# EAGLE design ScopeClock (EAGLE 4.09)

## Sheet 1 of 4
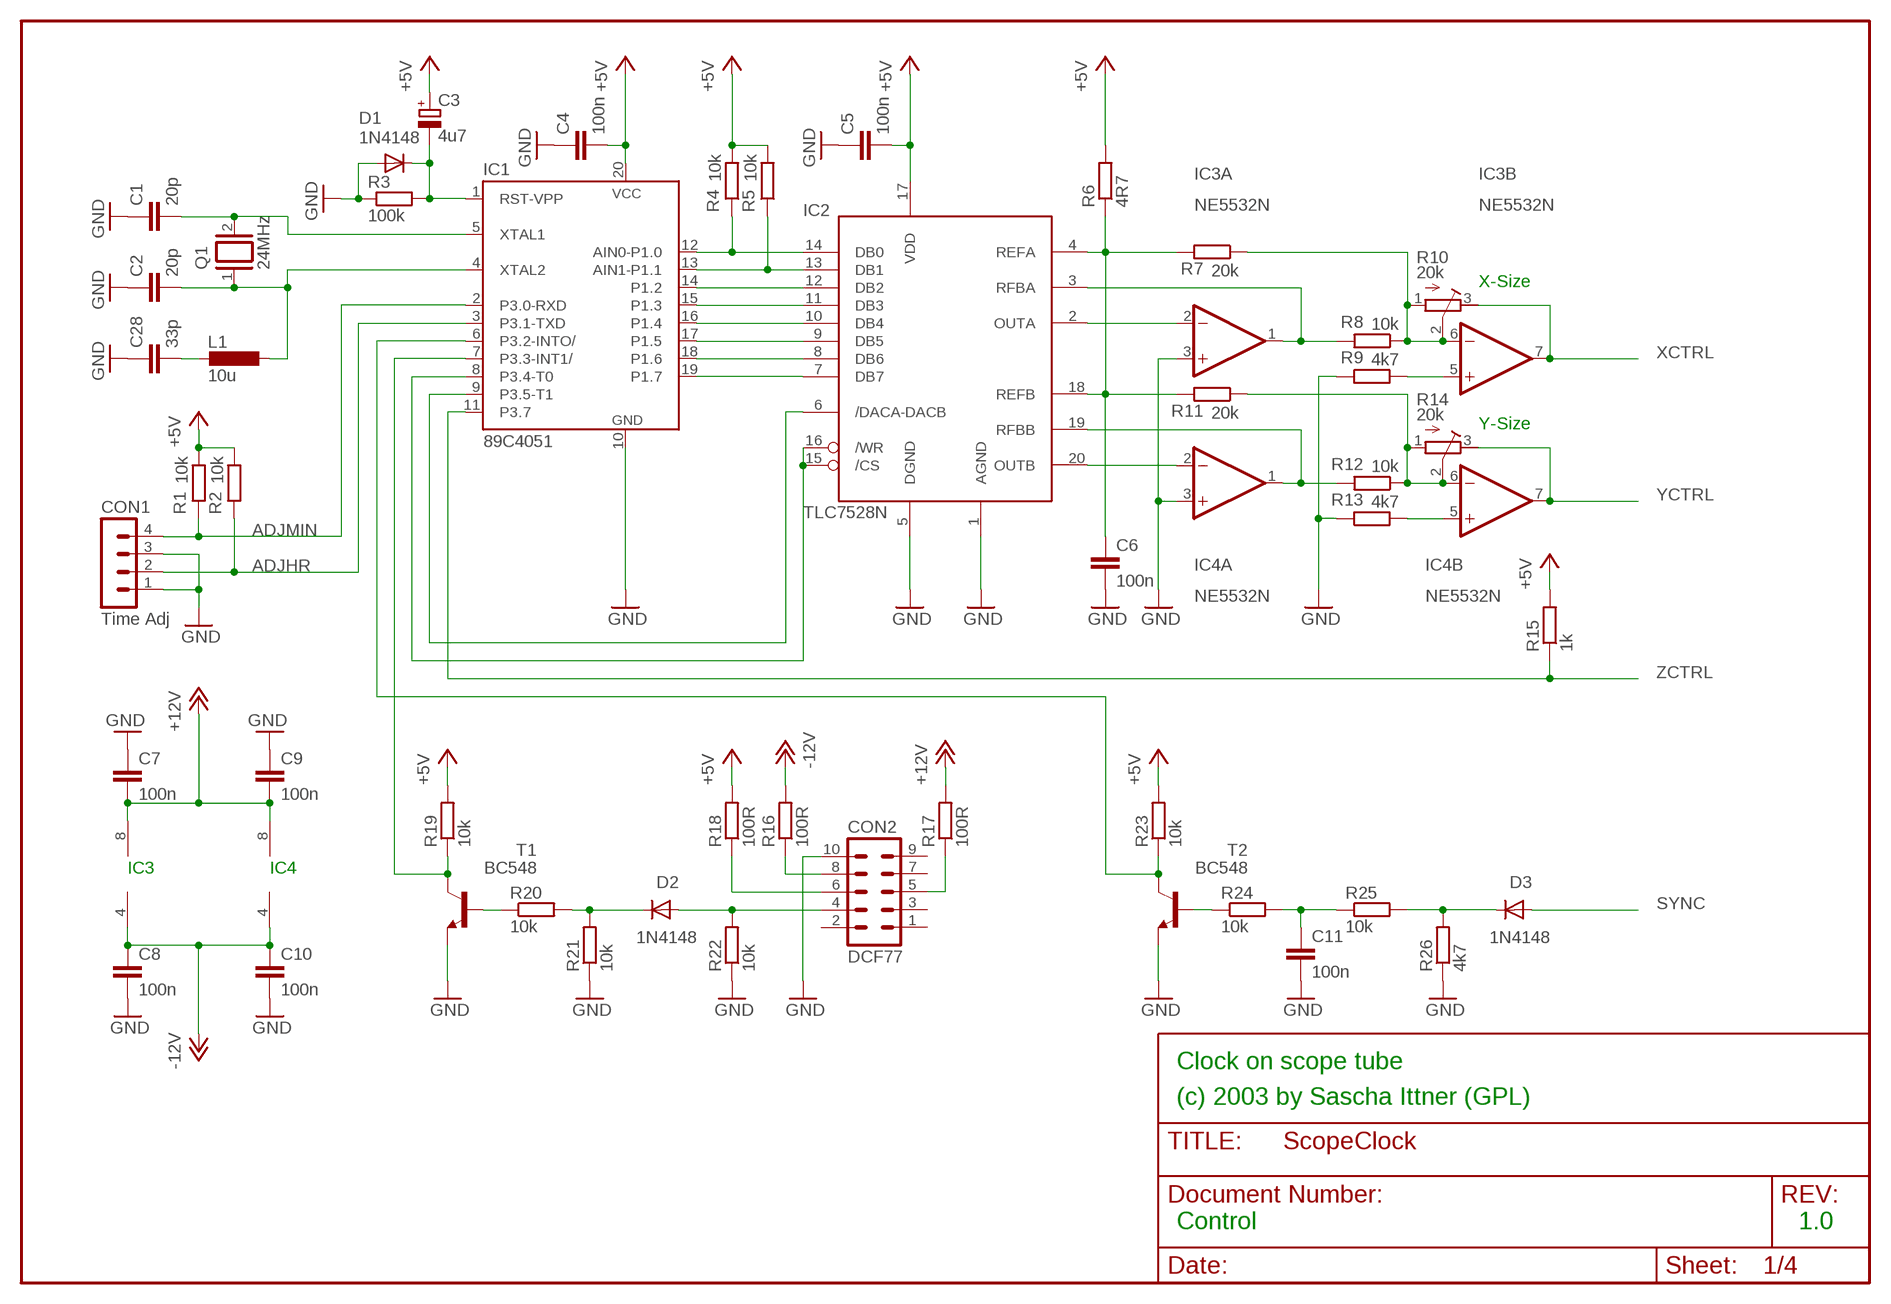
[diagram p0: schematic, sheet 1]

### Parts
C1  20p  C-EU025-024X044  [C025-024X044]
C2  20p  C-EU025-024X044  [C025-024X044]
C3  4u7  CPOL-EUE5-5  [E5-5]
C4  100n  C-EU050-024X044  [C050-024X044]
C5  100n  C-EU050-024X044  [C050-024X044]
C6  100n  C-EU050-024X044  [C050-024X044]
C7  100n  C-EU050-024X044  [C050-024X044]
C8  100n  C-EU050-024X044  [C050-024X044]
C9  100n  C-EU050-024X044  [C050-024X044]
C10  100n  C-EU050-024X044  [C050-024X044]
C11  100n  C-EU050-024X044  [C050-024X044]
C28  33p  C-EU025-024X044  [C025-024X044]
CON1  Time Adj  MA04-1  [MA04-1]
CON2  DCF77  ML10  [ML10]
D1  1N4148  [DO35-10]
D2  1N4148  [DO35-10]
D3  1N4148  [DO35-10]
IC1  89C4051  [DIL20]
IC2  TLC7528N  [DIL20]
IC3  NE5532N  [DIL08]
IC4  NE5532N  [DIL08]
L1  10u  L-EU0207/12  [0207/12]
Q1  24MHz  XTAL/S  [QS]
R1  10k  R-EU_0207/7  [0207/7]
R2  10k  R-EU_0207/7  [0207/7]
R3  100k  R-EU_0207/7  [0207/7]
R4  10k  R-EU_0207/7  [0207/7]
R5  10k  R-EU_0207/7  [0207/7]
R6  4R7  R-EU_0207/7  [0207/7]
R7  20k  R-EU_0207/7  [0207/7]
R8  10k  R-EU_0207/7  [0207/7]
R9  4k7  R-EU_0207/7  [0207/7]
R10  20k  R-TRIMM64W  [RTRIM64W]
R11  20k  R-EU_0207/7  [0207/7]
R12  10k  R-EU_0207/7  [0207/7]
R13  4k7  R-EU_0207/7  [0207/7]
R14  20k  R-TRIMM64W  [RTRIM64W]
R15  1k  R-EU_0207/7  [0207/7]
R16  100R  R-EU_0207/7  [0207/7]
R17  100R  R-EU_0207/7  [0207/7]
R18  100R  R-EU_0207/7  [0207/7]
R19  10k  R-EU_0207/7  [0207/7]
R20  10k  R-EU_0207/7  [0207/7]
R21  10k  R-EU_0207/7  [0207/7]
R22  10k  R-EU_0207/7  [0207/7]
R23  10k  R-EU_0207/7  [0207/7]
R24  10k  R-EU_0207/7  [0207/7]
R25  10k  R-EU_0207/7  [0207/7]
R26  4k7  R-EU_0207/7  [0207/7]
T1  BC548  [TO92-EBC]
T2  BC548  [TO92-EBC]

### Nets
+5V: C3.+ C4.2 C5.2 IC1.20(VCC) IC2.17(VDD) R1.2 R2.2 R4.2 R5.2 R6.2 R15.2 R18.2 R19.2 R23.2 ; also sheet 3
+12V: C7.2 C9.2 IC3.8(P:V+) IC4.8(P:V+) R17.2 ; also sheet 2,3
-12V: C8.1 C10.1 IC3.4(P:V-) IC4.4(P:V-) R16.2 ; also sheet 3
ADJHR: CON1.2 IC1.3(P3.1-TXD) R2.1
ADJMIN: CON1.4 IC1.2(P3.0-RXD) R1.1
GND: C1.1 C2.1 C4.1 C5.1 C6.2 C7.1 C8.2 C9.1 C10.2 C11.2 C28.1 CON1.1 CON1.3 CON2.10 D1.A IC1.10(GND) IC2.1(AGND) IC2.5(DGND) IC3.3(A:+IN) IC4.3(A:+IN) R3.1 R9.1 R13.1 R21.1 R22.1 R26.1 T1.E T2.E ; also sheet 2,3,4
N$1: IC1.12(AIN0-P1.0) IC2.14(DB0) R4.1
N$2: IC1.13(AIN1-P1.1) IC2.13(DB1) R5.1
N$3: IC1.14(P1.2) IC2.12(DB2)
N$4: IC1.15(P1.3) IC2.11(DB3)
N$5: IC1.16(P1.4) IC2.10(DB4)
N$6: IC1.17(P1.5) IC2.9(DB5)
N$7: IC1.18(P1.6) IC2.8(DB6)
N$8: IC1.19(P1.7) IC2.7(DB7)
N$9: IC1.9(P3.5-T1) IC2.6(/DACA-DACB)
N$10: IC1.8(P3.4-T0) IC2.15(/CS) IC2.16(/WR)
N$11: IC2.2(OUTA) IC3.2(A:-IN)
N$12: IC2.20(OUTB) IC4.2(A:-IN)
N$13: IC2.3(RFBA) IC3.1(A:OUT) R8.2
N$14: IC2.19(RFBB) IC4.1(A:OUT) R12.2
N$15: C6.1 IC2.4(REFA) IC2.18(REFB) R6.1 R7.2 R11.2
N$16: CON2.4 D2.A R22.2
N$17: IC3.5(B:+IN) R9.2
N$18: IC4.5(B:+IN) R13.2
N$19: IC3.6(B:-IN) R7.1 R8.1 R10.1(E) R10.2(S)
N$20: IC4.6(B:-IN) R11.1 R12.1 R14.1(E) R14.2(S)
N$21: C3.- D1.C IC1.1(RST-VPP) R3.2
N$25: C1.2 IC1.5(XTAL1) Q1.2
N$26: C2.2 IC1.4(XTAL2) L1.1 Q1.1
N$28: CON2.8 R16.1
N$29: CON2.6 R18.1
N$30: CON2.5 R17.1
N$31: IC1.6(P3.2-INTO/) R23.1 T2.C
N$32: C11.1 R24.2 R25.1
N$35: R20.1 T1.B
N$36: D2.C R20.2 R21.2
N$38: D3.C R25.2 R26.2
N$40: IC1.7(P3.3-INT1/) R19.1 T1.C
N$41: R24.1 T2.B
N$77: C28.2 L1.2
SYNC: D3.A ; also sheet 3
XCTRL: IC3.7(B:OUT) R10.3(A) ; also sheet 2
YCTRL: IC4.7(B:OUT) R14.3(A) ; also sheet 2
ZCTRL: IC1.11(P3.7) R15.1 ; also sheet 2
Unconnected: CON2.1 CON2.2 CON2.3 CON2.7 CON2.9

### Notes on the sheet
- X-Size
- Y-Size
- IC3 | IC4
- Clock on scope tube
- (c) 2003 by Sascha Ittner (GPL)
- Control | 1.0

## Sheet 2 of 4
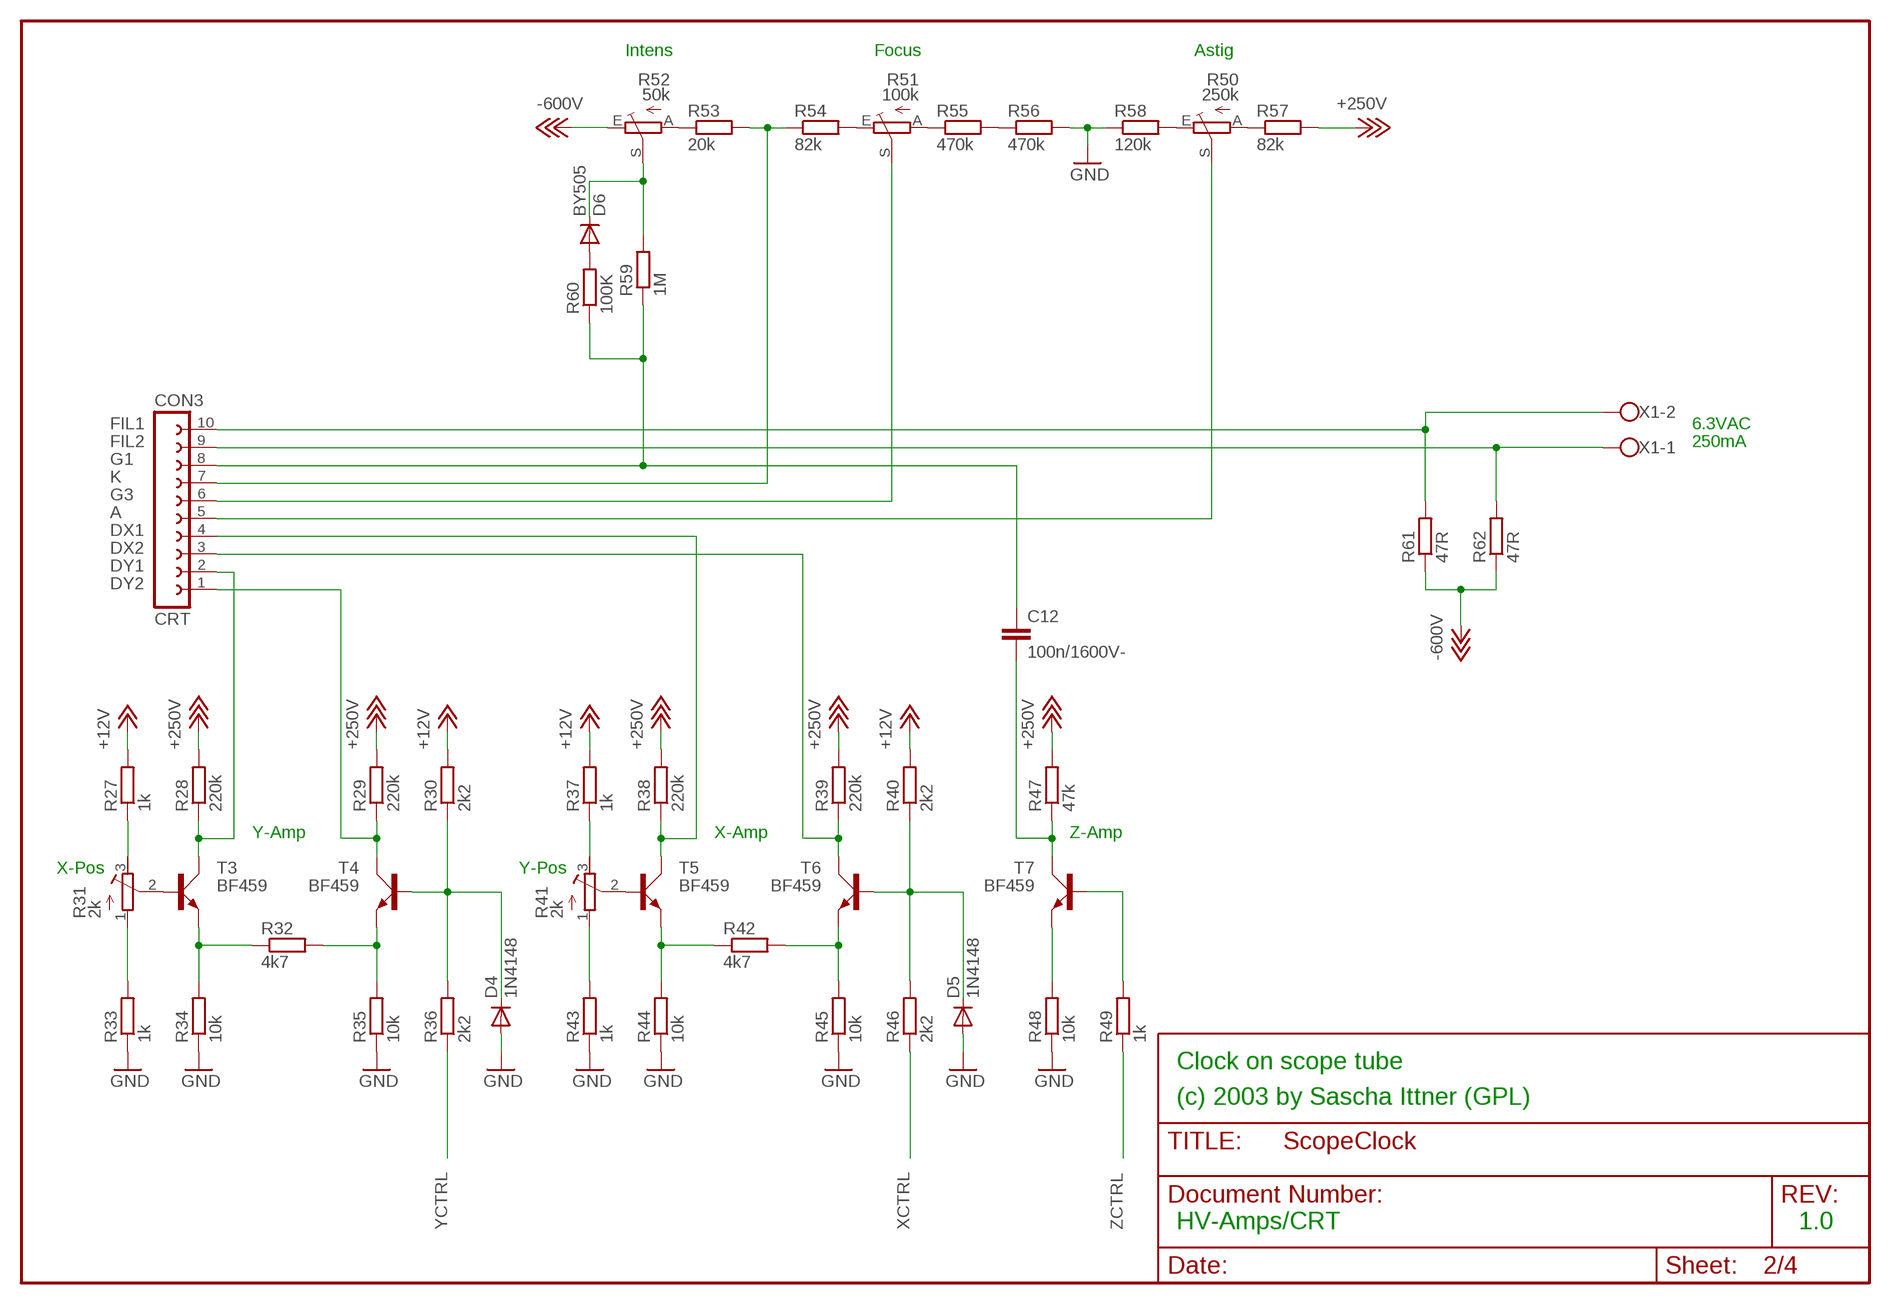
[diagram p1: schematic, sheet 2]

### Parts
C12  100n/1600V-  C-EU225-113X268  [C225-113X268]
CON3  CRT  FE10-1  [FE10]
D4  1N4148  [DO35-10]
D5  1N4148  [DO35-10]
D6  BY505  [SOD61A]
R27  1k  R-EU_0207/7  [0207/7]
R28  220k  R-EU_0207/7  [0207/7]
R29  220k  R-EU_0207/7  [0207/7]
R30  2k2  R-EU_0207/7  [0207/7]
R31  2k  R-TRIMM64W  [RTRIM64W]
R32  4k7  R-EU_0207/7  [0207/7]
R33  1k  R-EU_0207/7  [0207/7]
R34  10k  R-EU_0207/7  [0207/7]
R35  10k  R-EU_0207/7  [0207/7]
R36  2k2  R-EU_0207/7  [0207/7]
R37  1k  R-EU_0207/7  [0207/7]
R38  220k  R-EU_0207/7  [0207/7]
R39  220k  R-EU_0207/7  [0207/7]
R40  2k2  R-EU_0207/7  [0207/7]
R41  2k  R-TRIMM64W  [RTRIM64W]
R42  4k7  R-EU_0207/7  [0207/7]
R43  1k  R-EU_0207/7  [0207/7]
R44  10k  R-EU_0207/7  [0207/7]
R45  10k  R-EU_0207/7  [0207/7]
R46  2k2  R-EU_0207/7  [0207/7]
R47  47k  R-EU_0207/7  [0207/7]
R48  10k  R-EU_0207/7  [0207/7]
R49  1k  R-EU_0207/7  [0207/7]
R50  250k  TRIM_EU-S63P  [S63P]
R51  100k  TRIM_EU-S63P  [S63P]
R52  50k  TRIM_EU-S63P  [S63P]
R53  20k  R-EU_0207/7  [0207/7]
R54  82k  R-EU_0207/7  [0207/7]
R55  470k  R-EU_0207/7  [0207/7]
R56  470k  R-EU_0207/7  [0207/7]
R57  82k  R-EU_0207/7  [0207/7]
R58  120k  R-EU_0207/7  [0207/7]
R59  1M  R-EU_0207/7  [0207/7]
R60  100K  R-EU_0207/7  [0207/7]
R61  47R  R-EU_0207/7  [0207/7]
R62  47R  R-EU_0207/7  [0207/7]
T3  BF459  BD139  [TO126AV]
T4  BF459  BD139  [TO126AV]
T5  BF459  BD139  [TO126AV]
T6  BF459  BD139  [TO126AV]
T7  BF459  BD139  [TO126AV]
X1  W237-102  [W237-102]

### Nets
+12V: R27.2 R30.2 R37.2 R40.2 ; also sheet 1,3
+18V [HV]: R28.2 R29.2 R38.2 R39.2 R47.2 R57.2 ; supply symbol labelled +250V ; also sheet 4
-18V [VHV]: R52.E R61.1 R62.1 ; supply symbol labelled -600V ; also sheet 4
A [HV]: CON3.5 R50.S
DX1 [HV]: CON3.3 R39.1 T6.C
DX2 [HV]: CON3.4 R38.1 T5.C
DY1 [HV]: CON3.1 R29.1 T4.C
DY2 [HV]: CON3.2 R28.1 T3.C
FIL1 [VHV]: CON3.10 R61.2 X1.2
FIL2 [VHV]: CON3.9 R62.2 X1.1
G1 [VHV]: C12.1 CON3.8 R59.1 R60.1
G3: CON3.6 R51.S
GND: D4.A D5.A R33.1 R34.1 R35.1 R43.1 R44.1 R45.1 R48.1 R56.2 R58.1 ; also sheet 1,3,4
K [VHV]: CON3.7 R53.2 R54.1
N$22: R31.2(S) T3.B
N$23: R31.1(E) R33.2
N$24: R32.1 R34.2 T3.E
N$27: R41.2(S) T5.B
N$33: R32.2 R35.2 T4.E
N$34: R41.1(E) R43.2
N$37: D4.C R30.1 R36.2 T4.B
N$43: R27.1 R31.3(A)
N$44: R42.1 R44.2 T5.E
N$45: R37.1 R41.3(A)
N$46: R42.2 R45.2 T6.E
N$48: D5.C R40.1 R46.2 T6.B
N$49: R48.2 T7.E
N$50 [HV]: C12.2 R47.1 T7.C
N$52 [VHV]: R52.A R53.1
N$53 [VHV]: R51.E R54.2
N$54: R49.2 T7.B
N$55 [VHV]: R51.A R55.1
N$56 [HV]: R50.A R57.1
N$57 [HV]: R55.2 R56.1
N$58 [HV]: R50.E R58.2
N$69 [VHV]: D6.A R60.2
N$70 [VHV]: D6.C R52.S R59.2
XCTRL: R46.1 ; also sheet 1
YCTRL: R36.1 ; also sheet 1
ZCTRL: R49.1 ; also sheet 1

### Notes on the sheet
- Intens | Focus | Astig
- 6.3VAC
- 250mA
- Y-Amp | X-Amp | Z-Amp
- X-Pos | Y-Pos
- Clock on scope tube
- (c) 2003 by Sascha Ittner (GPL)
- HV-Amps/CRT | 1.0

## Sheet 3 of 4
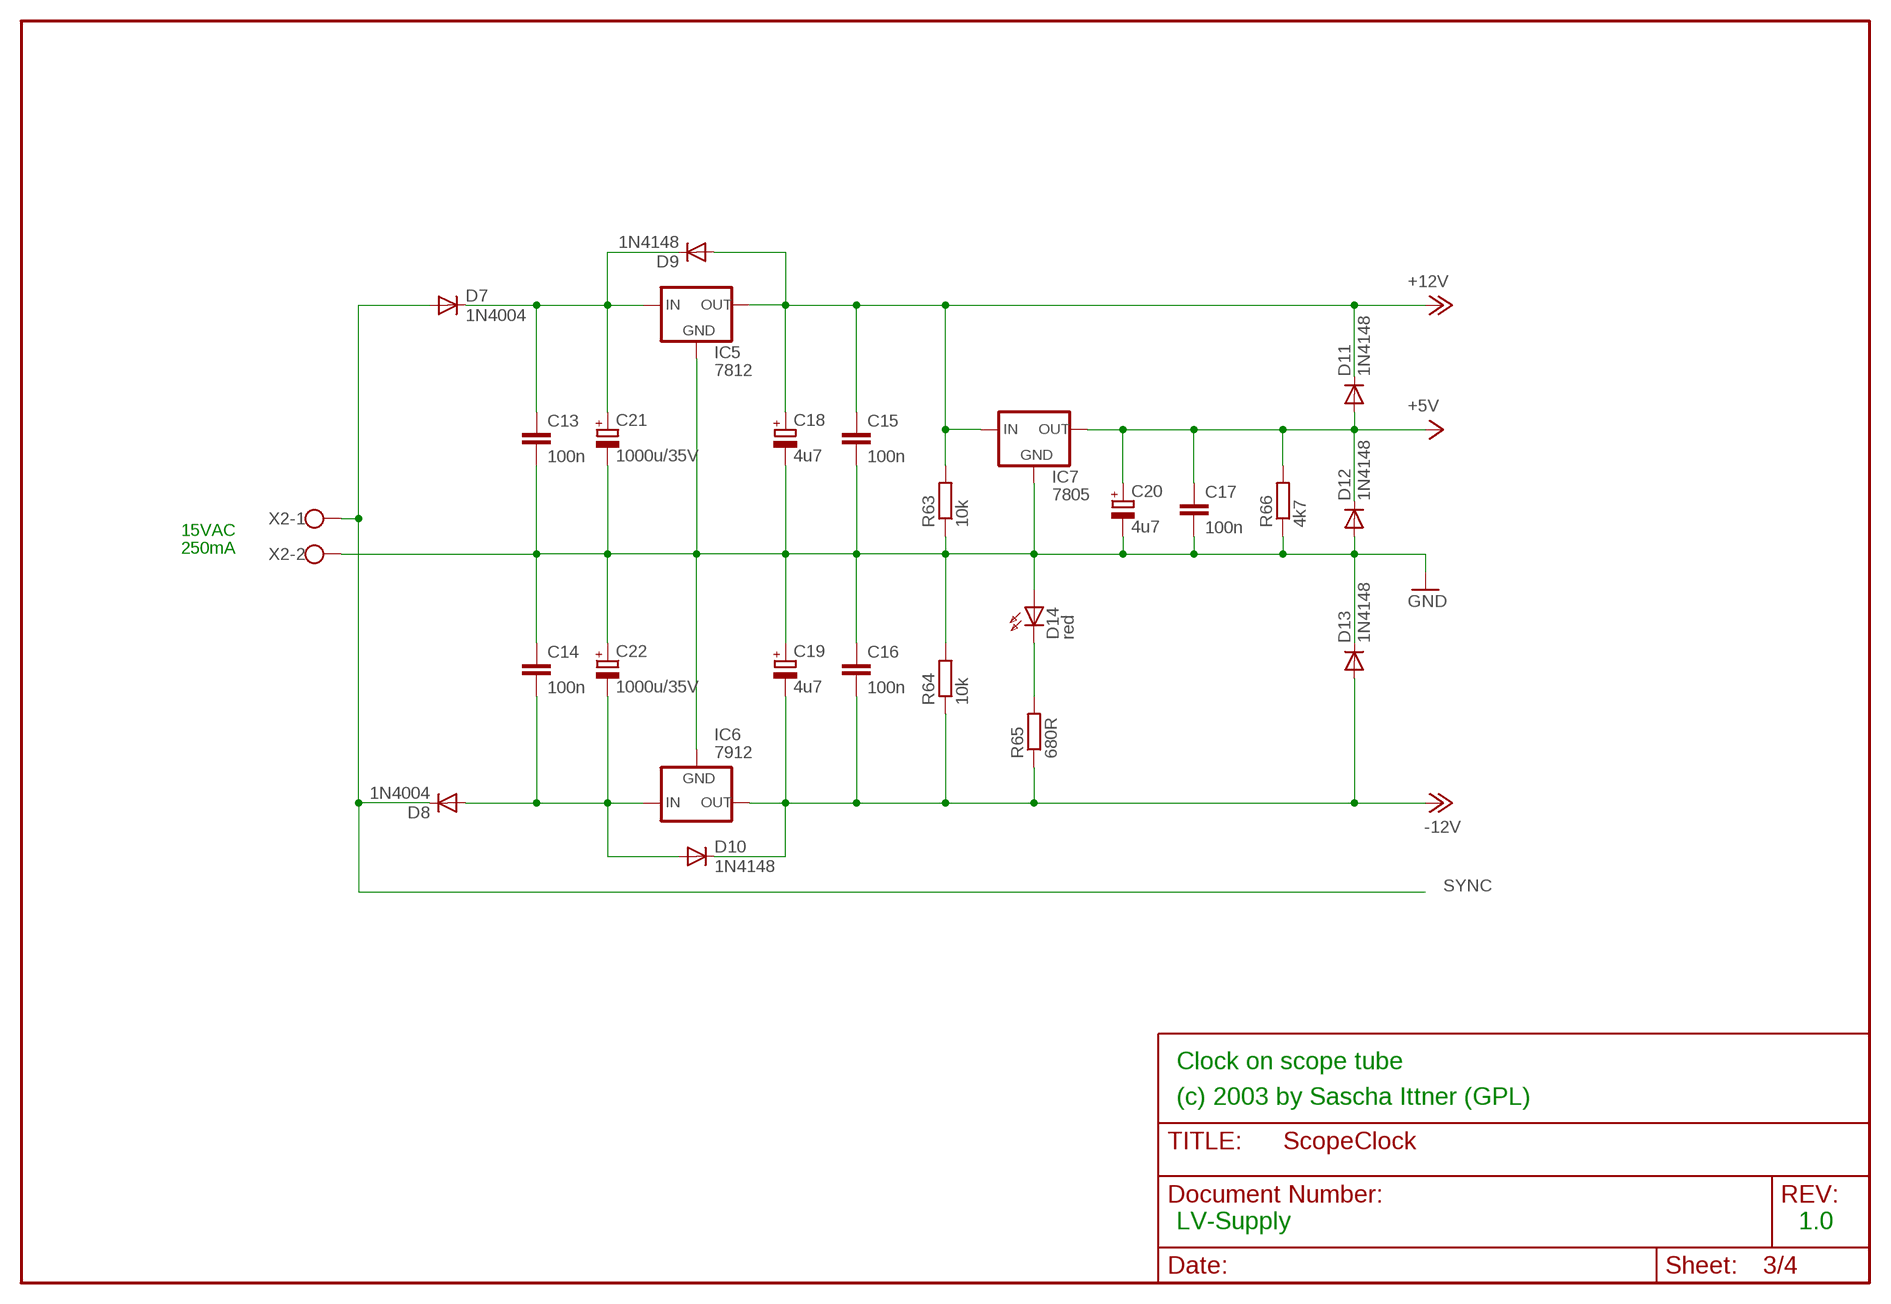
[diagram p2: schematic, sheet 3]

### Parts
C13  100n  C-EU050-024X044  [C050-024X044]
C14  100n  C-EU050-024X044  [C050-024X044]
C15  100n  C-EU050-024X044  [C050-024X044]
C16  100n  C-EU050-024X044  [C050-024X044]
C17  100n  C-EU050-024X044  [C050-024X044]
C18  4u7  CPOL-EUE2.5-5  [E2,5-5]
C19  4u7  CPOL-EUE2.5-5  [E2,5-5]
C20  4u7  CPOL-EUE2.5-5  [E2,5-5]
C21  1000u/35V  CPOL-EUE5-13  [E5-13]
C22  1000u/35V  CPOL-EUE5-13  [E5-13]
D7  1N4004  [DO41-10]
D8  1N4004  [DO41-10]
D9  1N4148  [DO35-10]
D10  1N4148  [DO35-10]
D11  1N4148  [DO35-10]
D12  1N4148  [DO35-10]
D13  1N4148  [DO35-10]
D14  red  LED3MM  [LED3MM]
IC5  7812  78XXS  [78XXS]
IC6  7912  79XXS  [79XXS]
IC7  7805  78XXS  [78XXS]
R63  10k  R-EU_0207/7  [0207/7]
R64  10k  R-EU_0207/7  [0207/7]
R65  680R  R-EU_0207/7  [0207/7]
R66  4k7  R-EU_0207/7  [0207/7]
X2  W237-102  [W237-102]

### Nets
+5V: C17.1 C20.+ D11.A D12.C IC7.OUT R66.2 ; also sheet 1
+12V: C15.1 C18.+ D9.A D11.C IC5.OUT IC7.IN R63.2 ; also sheet 1,2
-12V: C16.2 C19.- D10.C D13.A IC6.OUT R64.1 R65.1 ; also sheet 1
GND: C13.2 C14.1 C15.2 C16.1 C17.2 C18.- C19.+ C20.- C21.- C22.+ D12.A D13.C D14.A IC5.GND IC6.GND IC7.GND R63.1 R64.2 R66.1 X2.2 ; also sheet 1,2,4
N$63: D14.K(C) R65.2
N$68: C13.1 C21.+ D7.C D9.C IC5.IN
N$75: C14.2 C22.- D8.A D10.A IC6.IN
SYNC: D7.A D8.C X2.1 ; also sheet 1

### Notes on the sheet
- 15VAC
- 250mA
- Clock on scope tube
- (c) 2003 by Sascha Ittner (GPL)
- LV-Supply | 1.0

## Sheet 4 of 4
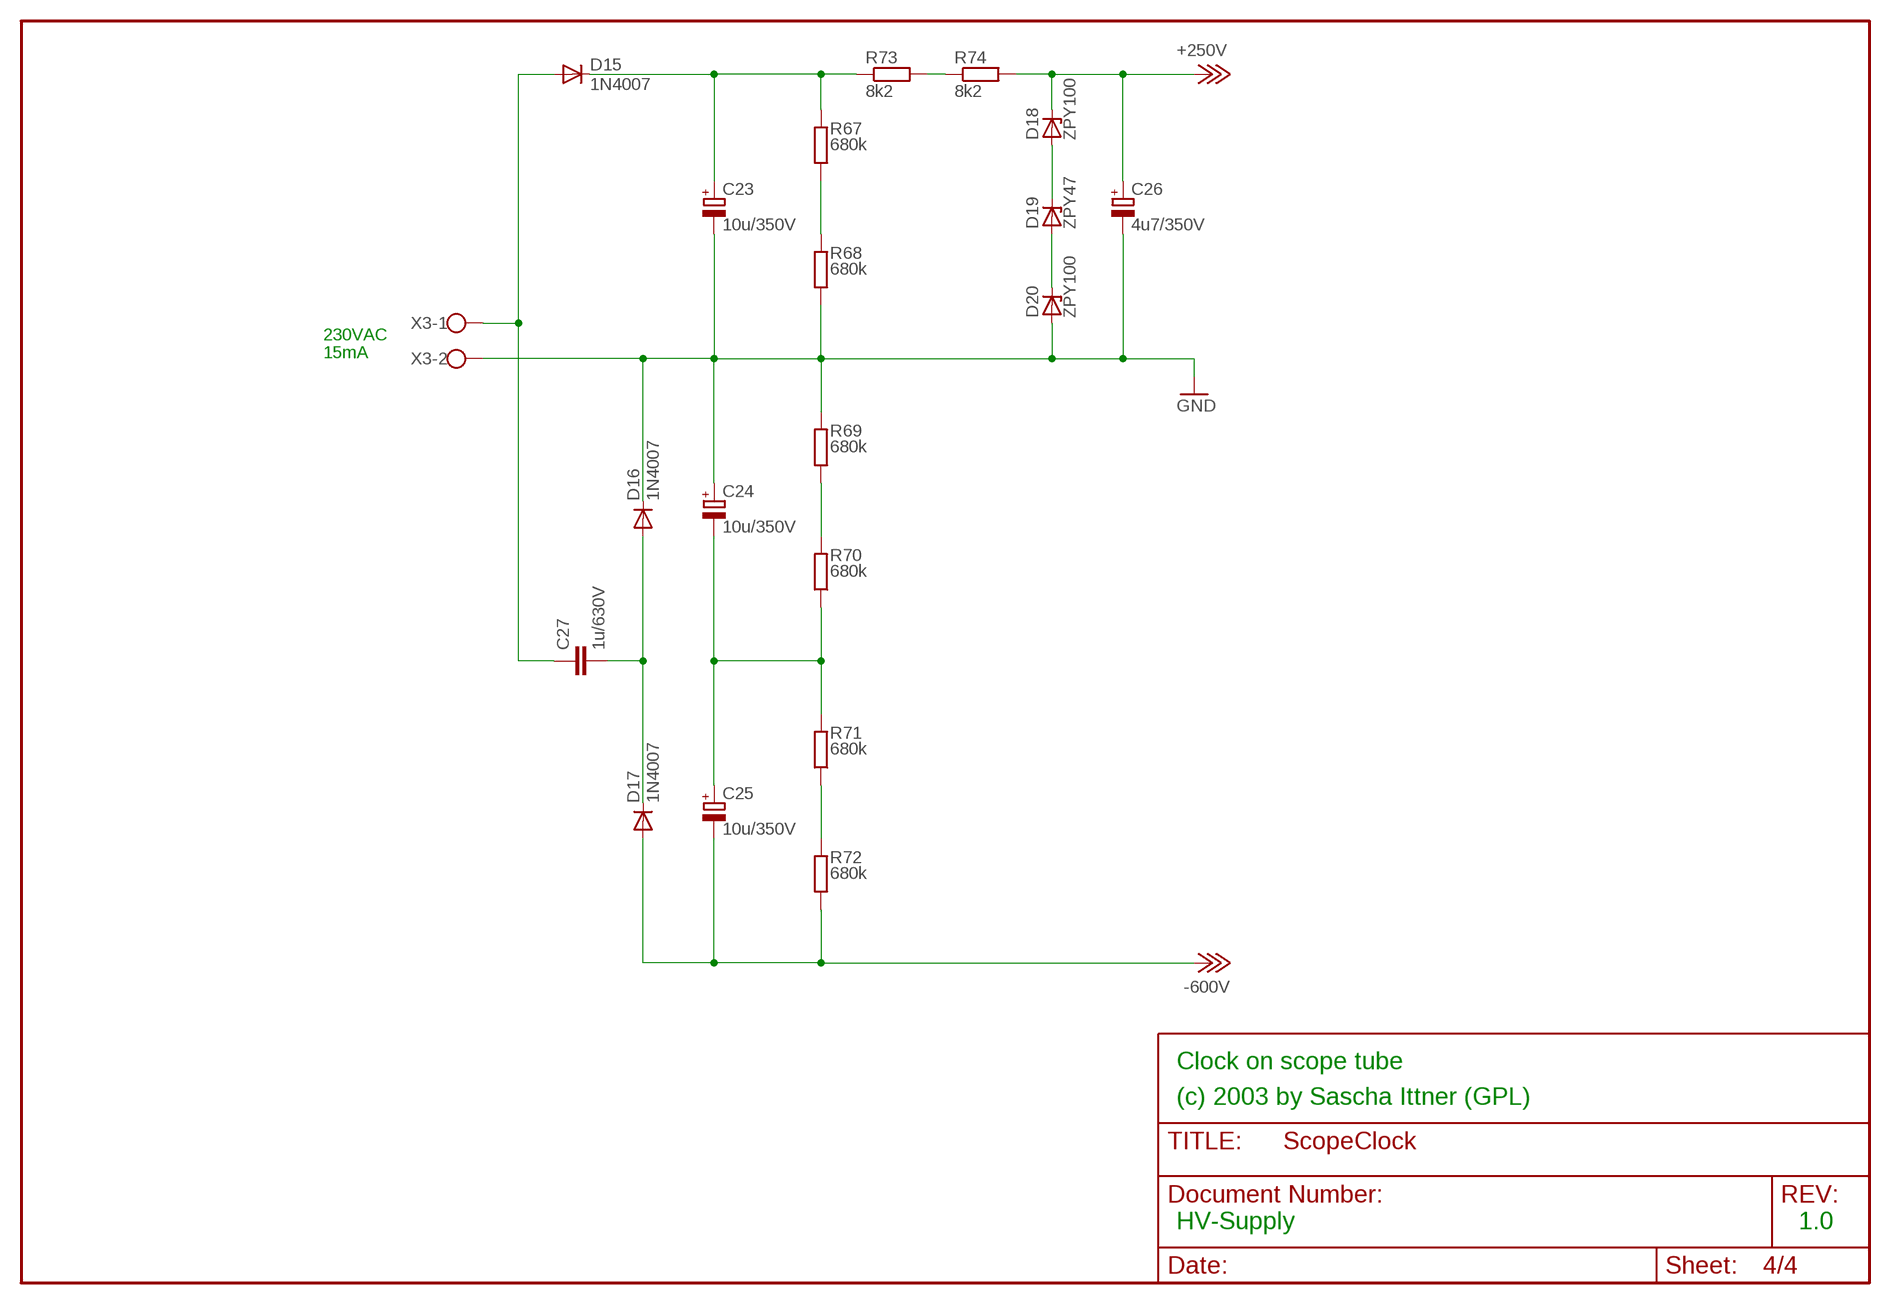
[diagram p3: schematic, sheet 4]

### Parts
C23  10u/350V  CPOL-EUE5-13  [E5-13]
C24  10u/350V  CPOL-EUE5-13  [E5-13]
C25  10u/350V  CPOL-EUE5-13  [E5-13]
C26  4u7/350V  CPOL-EUE5-10.5  [E5-10,5]
C27  1u/630V  C-EU275-173X316  [C275-173X316]
D15  1N4007  1N4004  [DO41-10]
D16  1N4007  1N4004  [DO41-10]
D17  1N4007  1N4004  [DO41-10]
D18  ZPY100  ZPY  [DO41Z10]
D19  ZPY47  ZPY  [DO41Z10]
D20  ZPY100  ZPY  [DO41Z10]
R67  680k  R-EU_0207/7  [0207/7]
R68  680k  R-EU_0207/7  [0207/7]
R69  680k  R-EU_0207/7  [0207/7]
R70  680k  R-EU_0207/7  [0207/7]
R71  680k  R-EU_0207/7  [0207/7]
R72  680k  R-EU_0207/7  [0207/7]
R73  8k2  R-EU_0207/7  [0207/7]
R74  8k2  R-EU_0207/7  [0207/7]
X3  W237-113  [W237-113]

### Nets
+18V [HV]: C26.+ D18.C R74.2 ; supply symbol labelled +250V ; also sheet 2
-18V [VHV]: C25.- D17.A R72.1 ; supply symbol labelled -600V ; also sheet 2
GND: C23.- C24.+ C26.- D16.C D20.A R68.1 R69.2 X3.2 ; also sheet 1,2,3
N$39 [HV]: D18.A D19.C
N$42 [HV]: D19.A D20.C
N$64 [HV]: R73.2 R74.1
N$65 [HV]: C23.+ D15.C R67.2 R73.1
N$67 [HV]: R67.1 R68.2
N$72 [HV]: C24.- C25.+ R70.1 R71.2
N$74 [VHV]: R69.1 R70.2
N$78 [VHV]: R71.1 R72.2
N$80 [VHV]: C27.2 D16.A D17.C
N$82 [HV]: C27.1 D15.A X3.1

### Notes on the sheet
- 230VAC
- 15mA
- Clock on scope tube
- (c) 2003 by Sascha Ittner (GPL)
- HV-Supply | 1.0

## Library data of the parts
C1 C2 C4-C17 C27 C28 = rcl:C-EU: CAPACITOR, European symbol
C3 C18-C26 = rcl:CPOL-EU: POLARIZED CAPACITOR, European symbol
CON1 = con-lstb:MA04-1: PIN HEADER
CON2 = con-harting-ml:ML10: HARTING
CON3 = con-lsta:FE10-1: FEMALE HEADER
D1-D5 D9-D13 = diode:1N4148: DIODE
D6 = diode:BY505: DIODE
D7 D8 D15-D17 = diode:1N4004: DIODE
D14 = led:LED: LED
D18-D20 = diode:ZPY: Z DIODE
IC1 = clock:89C4051: Atmel 89C4051 8-Bit Microcontroller with 4K Bytes Flash
IC2 = clock:TLC7528*: TI TLC7528 Dual 8-Bit multiplying DAC
IC3 IC4 = linear:NE5532: AUDIO AMPLIFIER
IC5 IC7 = v-reg:78XXS: VOLTAGE REGULATOR
IC6 = v-reg:79XXS: VOLTAGE REGULATOR
L1 = rcl:L-EU: INDUCTOR, European symbol
Q1 = special:XTAL/S: CRYSTAL
R1-R9 R11-R13 R15-R30 R32-R40 R42-R49 R53-R74 = rcl:R-EU_: RESISTOR, European symbol
R10 R14 R31 R41 = rcl:R-TRIMM: Trimm resistor
R50-R52 = pot:TRIM_EU-: POTENTIOMETER
T1 T2 = transistor-npn:BC548*: NPN Transistor
T3-T7 = transistor-power:BD139: NPN TRANSISTOR
X1 X2 = con-wago-500:W237-102: WAGO SCREW CLAMP
X3 = con-wago-500:W237-113: WAGO SCREW CLAMP

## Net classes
0 default: drill 0.203 mm
1 HV: drill 1.143 mm
2 VHV: drill 1.905 mm

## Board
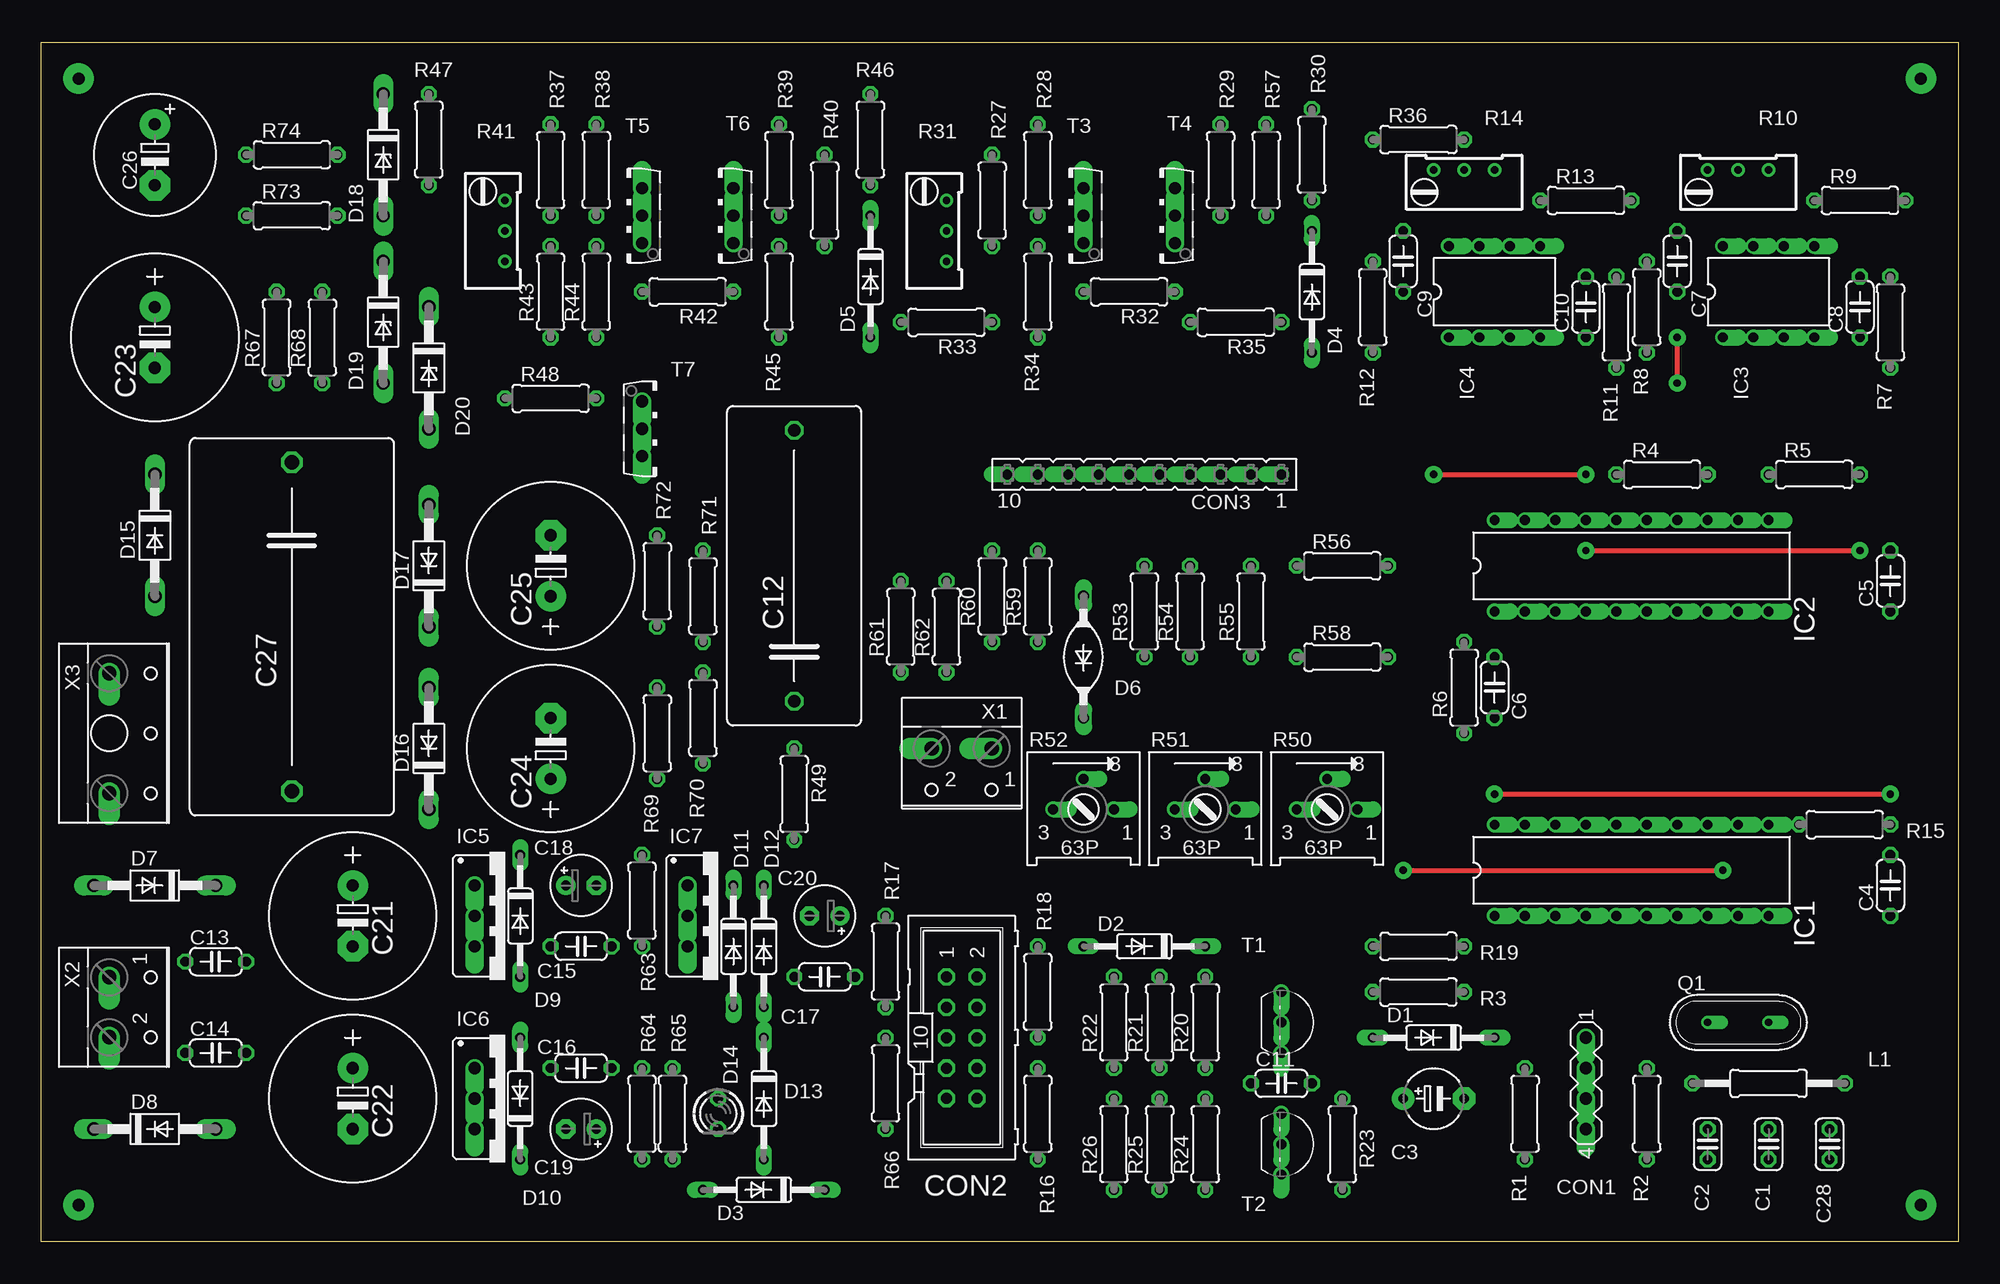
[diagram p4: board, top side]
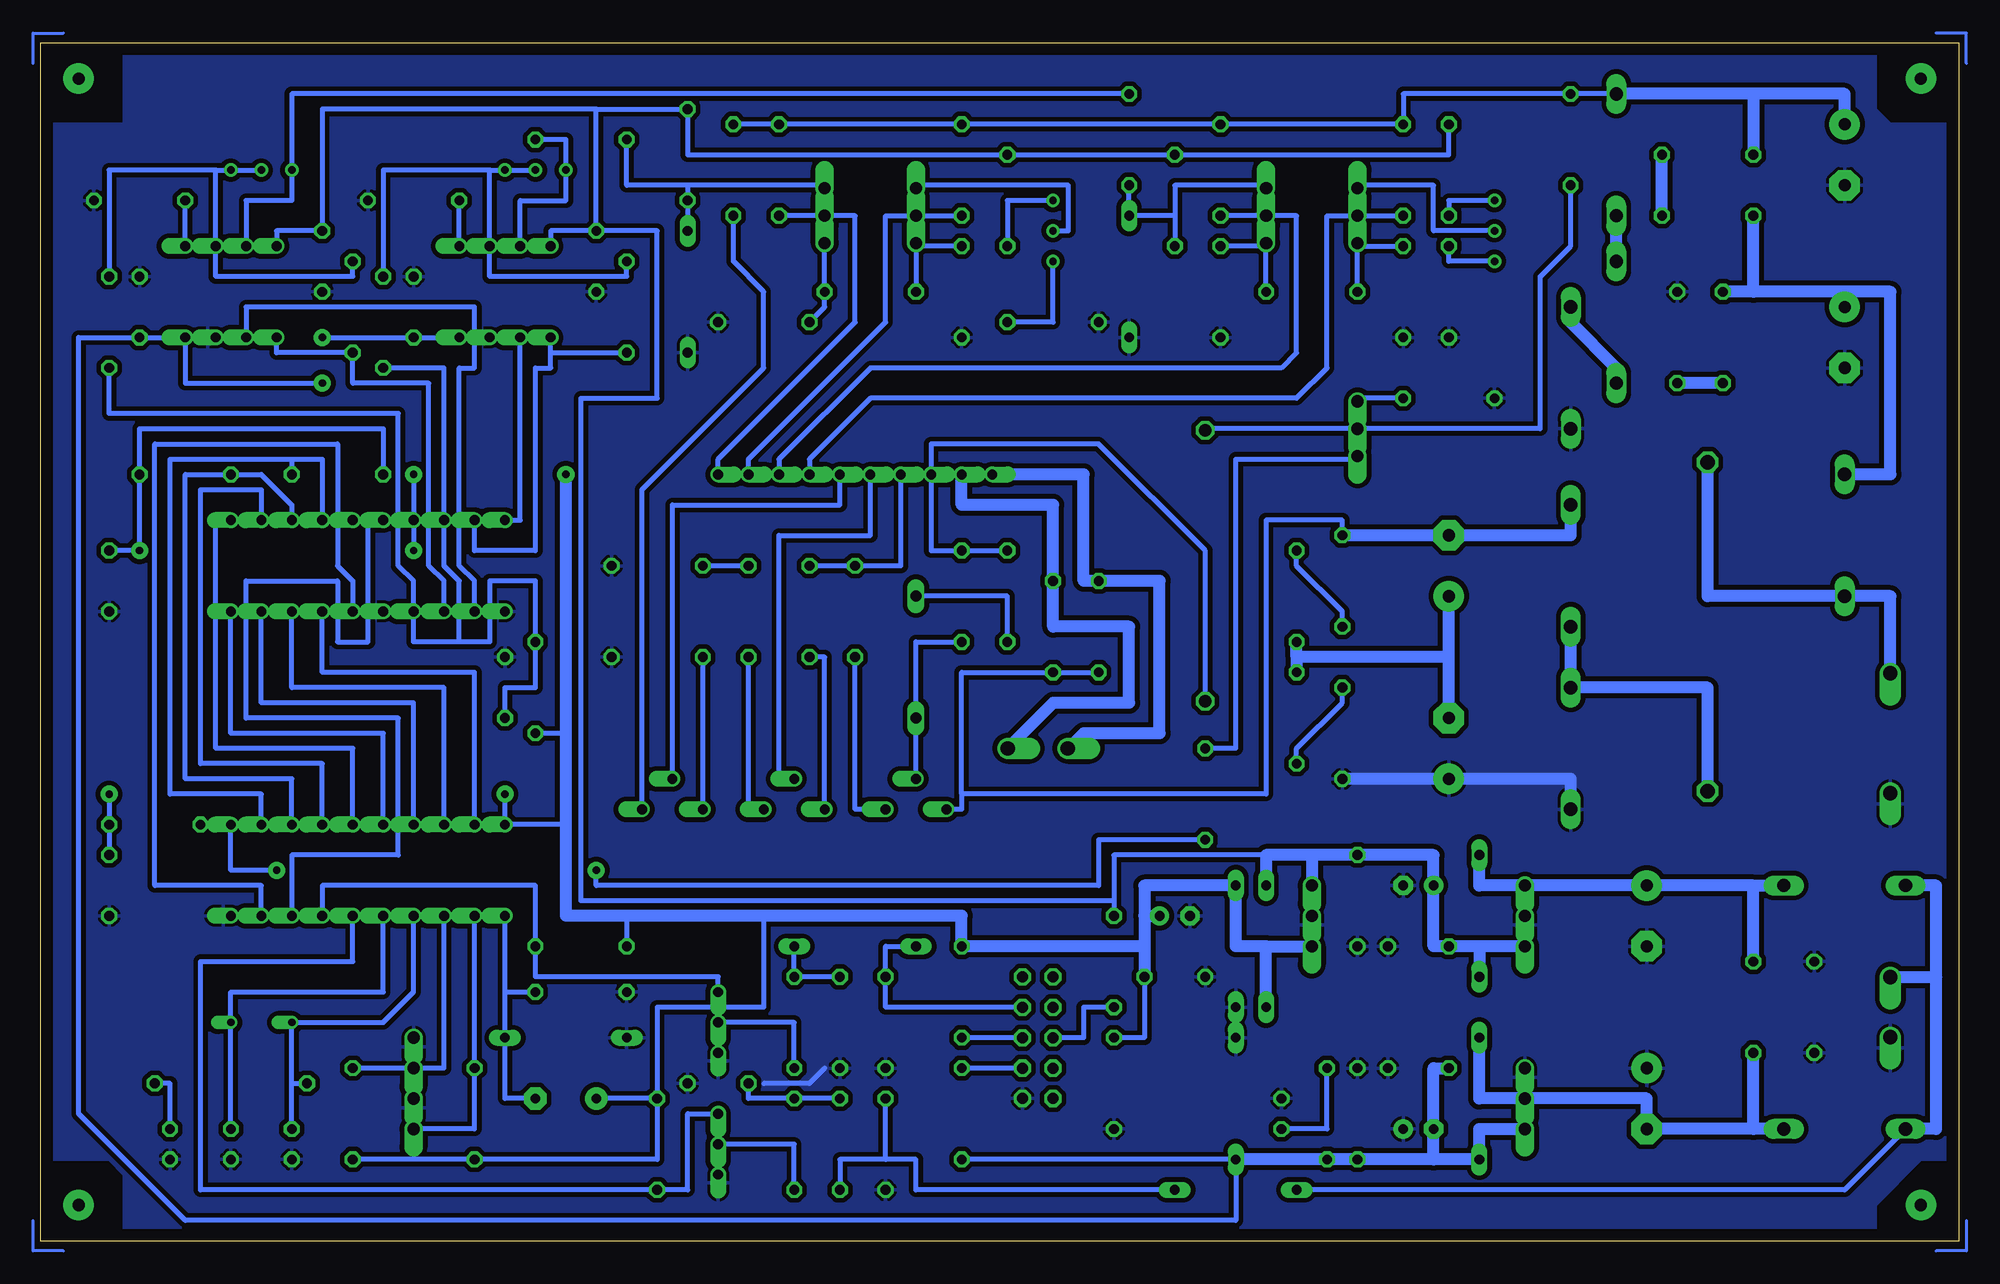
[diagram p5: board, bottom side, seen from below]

Size 160 x 100 mm. Coordinates in mm from the lower left corner, seen from the top.
Outline: 0,0 160,0 160,100 0,100 0,0
Copper layers used: Top, Bottom

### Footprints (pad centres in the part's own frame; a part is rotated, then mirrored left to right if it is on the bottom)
C025-024X044 = drill 0.813 octagon: 1 -1.27,0; 2 1.27,0
E5-5 = drill 0.813 pad 1.905 round: + -2.54,0 | drill 0.813 pad 1.905 octagon: - 2.54,0
C050-024X044 = drill 0.813 octagon: 1 -2.54,0; 2 2.54,0
C225-113X268 = drill 1.016 octagon: 1 -11.303,0; 2 11.303,0
E2,5-5 = drill 0.813 pad 1.6 round: + -1.27,0 | drill 0.813 pad 1.6 octagon: - 1.27,0
E5-13 = drill 1.016 pad 2.54 round: + -2.54,0 | drill 1.016 pad 2.54 octagon: - 2.54,0
E5-10,5 = drill 1.016 pad 2.54 round: + -2.54,0 | drill 1.016 pad 2.54 octagon: - 2.54,0
C275-173X316 = drill 1.194 octagon: 1 -13.716,0; 2 13.716,0
MA04-1 = drill 1.016 offset: 1 -3.81,0; 2 -1.27,0; 3 1.27,0; 4 3.81,0
ML10 = drill 0.914 octagon: 1 -5.08,-1.27; 2 -5.08,1.27; 3 -2.54,-1.27; 4 -2.54,1.27; 5 0,-1.27; 6 0,1.27; 7 2.54,-1.27; 8 2.54,1.27; 9 5.08,-1.27; 10 5.08,1.27
FE10 = drill 0.813 offset: 1 -11.43,0; 2 -8.89,0; 3 -6.35,0; 4 -3.81,0; 5 -1.27,0; 6 1.27,0; 7 3.81,0; 8 6.35,0; 9 8.89,0; 10 11.43,0
DO35-10 = drill 0.813 long: A 5.08,0; C -5.08,0
SOD61A = drill 0.914 long: A 5.08,0; C -5.08,0
DO41-10 = drill 1.118 long: A 5.08,0; C -5.08,0
LED3MM = drill 0.813 octagon: A -1.27,0; K 1.27,0
DO41Z10 = drill 1.118 long: A 5.08,0; C -5.08,0
DIL20 = drill 0.813 offset: 1 -11.43,-3.81; 2 -8.89,-3.81; 3 -6.35,-3.81; 4 -3.81,-3.81; 5 -1.27,-3.81; 6 1.27,-3.81; 7 3.81,-3.81; 8 6.35,-3.81; 9 8.89,-3.81; 10 11.43,-3.81; 11 11.43,3.81; 12 8.89,3.81; 13 6.35,3.81; 14 3.81,3.81; 15 1.27,3.81; 16 -1.27,3.81; 17 -3.81,3.81; 18 -6.35,3.81; 19 -8.89,3.81; 20 -11.43,3.81
DIL08 = drill 0.813 offset: 1 -3.81,-3.81; 2 -1.27,-3.81; 3 1.27,-3.81; 4 3.81,-3.81; 5 3.81,3.81; 6 1.27,3.81; 7 -1.27,3.81; 8 -3.81,3.81
78XXS = drill 1.016 offset: GND 0,-2.54; IN -2.54,-2.54; OUT 2.54,-2.54
79XXS = drill 1.016 offset: GND -2.54,-2.54; IN 0,-2.54; OUT 2.54,-2.54
0207/12 = drill 0.813 octagon: 1 -6.35,0; 2 6.35,0
QS = drill 0.61 offset: 1 -2.54,0; 2 2.54,0
0207/7 = drill 0.813 octagon: 1 -3.81,0; 2 3.81,0
RTRIM64W = drill 0.61 round: 1 1.27,-2.54; 2 1.27,0; 3 1.27,2.54
S63P = drill 0.813 offset: A 2.54,0; E -2.54,0; S 0,2.54
TO92-EBC = drill 0.813 offset: B 0,-1.27; C -2.54,-1.27; E 2.54,-1.27
TO126AV = drill 1.016 offset: B 2.286,-1.27; C 0,-1.27; E -2.286,-1.27
W237-102 = drill 1.194 offset: 1 -2.5,-1.27; 2 2.5,-1.27
W237-113 = drill 1.194 offset: 1 -5,-1.27; 2 5,-1.27

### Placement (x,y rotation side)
C1  144.14,8.09 90 top
C2  139.06,8.09 90 top
C3  116.2,11.9 0 top
C4  154.3,29.68 90 top
C5  154.3,55.08 90 top
C6  121.28,46.19 90 top
C7  136.52,81.75 90 top
C8  151.76,77.94 90 top
C9  113.66,81.75 90 top
C10  128.9,77.94 90 top
C11  103.5,13.17 0 top
C12  62.86,56.35 90 top
C13  14.6,23.33 180 top
C14  14.6,15.71 0 top
C15  45.08,24.6 0 top
C16  45.08,14.44 180 top
C17  65.4,22.06 180 top
C18  45.08,29.68 0 top
C19  45.08,9.36 180 top
C20  65.4,27.14 180 top
C21  26.03,27.14 270 top
C22  26.03,11.9 270 top
C23  9.52,75.4 270 top
C24  42.54,41.11 90 top
C25  42.54,56.35 90 top
C26  9.52,90.64 270 top
C27  20.95,51.27 270 top
C28  149.22,8.09 90 top
CON1  128.9,13.17 270 top
CON2  76.83,16.98 270 top
CON3  92.07,63.97 180 top
D1  116.2,16.98 180 top
D2  92.07,24.6 180 top
D3  60.32,4.28 180 top
D4  106.04,79.21 270 top
D5  69.21,80.48 270 top
D6  86.99,48.73 90 top
D7  9.52,29.68 180 top
D8  9.52,9.36 0 top
D9  40,27.14 270 top
D10  40,11.9 90 top
D11  57.78,24.6 270 top
D12  60.32,24.6 270 top
D13  60.32,11.9 270 top
D14  56.51,10.63 270 top
D15  9.52,58.89 270 top
D16  32.38,41.11 90 top
D17  32.38,56.35 90 top
D18  28.57,90.64 270 top
D19  28.57,76.67 270 top
D20  32.38,72.86 270 top
IC1  132.71,30.95 0 top
IC2  132.71,56.35 0 top
IC3  144.14,79.21 0 top
IC4  121.28,79.21 0 top
IC5  38.73,27.14 270 top
IC6  38.73,11.9 270 top
IC7  56.51,27.14 270 top
L1  144.14,13.17 0 top
Q1  141.6,18.25 0 top
R1  123.82,10.63 270 top
R2  133.98,10.63 270 top
R3  114.93,20.79 0 top
R4  135.25,63.97 180 top
R5  147.95,63.97 0 top
R6  118.74,46.19 270 top
R7  154.3,76.67 270 top
R8  133.98,77.94 270 top
R9  151.76,86.83 180 top
R10  141.6,88.1 90 top
R11  131.44,76.67 270 top
R12  111.12,77.94 270 top
R13  128.9,86.83 180 top
R14  118.74,88.1 90 top
R15  150.49,34.76 0 top
R16  83.18,10.63 270 top
R17  70.48,23.33 90 top
R18  83.18,20.79 90 top
R19  114.93,24.6 180 top
R20  97.15,18.25 90 top
R21  93.34,18.25 90 top
R22  89.53,18.25 90 top
R23  108.58,8.09 90 top
R24  97.15,8.09 90 top
R25  93.34,8.09 270 top
R26  89.53,8.09 90 top
R27  79.37,86.83 90 top
R28  83.18,89.37 90 top
R29  98.42,89.37 90 top
R30  106.04,90.64 90 top
R31  74.29,84.29 0 top
R32  90.8,79.21 0 top
R33  75.56,76.67 0 top
R34  83.18,79.21 90 top
R35  99.69,76.67 180 top
R36  114.93,91.91 180 top
R37  42.54,89.37 90 top
R38  46.35,89.37 90 top
R39  61.59,89.37 90 top
R40  65.4,86.83 90 top
R41  37.46,84.29 0 top
R42  53.97,79.21 0 top
R43  42.54,79.21 90 top
R44  46.35,79.21 90 top
R45  61.59,79.21 90 top
R46  69.21,91.91 270 top
R47  32.38,91.91 90 top
R48  42.54,70.32 0 top
R49  62.86,37.3 90 top
R50  107.31,36.03 0 top
R51  97.15,36.03 0 top
R52  86.99,36.03 0 top
R53  92.07,52.54 90 top
R54  95.88,52.54 270 top
R55  100.96,52.54 90 top
R56  108.58,56.35 0 top
R57  102.23,89.37 90 top
R58  108.58,48.73 180 top
R59  83.18,53.81 270 top
R60  79.37,53.81 270 top
R61  71.75,51.27 90 top
R62  75.56,51.27 90 top
R63  50.16,28.41 90 top
R64  50.16,10.63 90 top
R65  52.7,10.63 90 top
R66  70.48,13.17 90 top
R67  19.68,75.4 90 top
R68  23.49,75.4 270 top
R69  51.43,42.38 270 top
R70  55.24,43.65 270 top
R71  55.24,53.81 270 top
R72  51.43,55.08 270 top
R73  20.95,85.56 0 top
R74  20.95,90.64 180 top
T1  104.77,18.25 270 top
T2  104.77,8.09 270 top
T3  85.72,85.56 90 top
T4  93.34,85.56 90 top
T5  48.89,85.56 90 top
T6  56.51,85.56 90 top
T7  51.43,67.78 270 top
X1  76.83,39.84 180 top
X2  6.98,19.52 270 top
X3  6.98,42.38 270 top

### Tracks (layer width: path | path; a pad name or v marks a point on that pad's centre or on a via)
+5V  (via drill 0.61 pad 1.42)
  Top 0.406: v121.28,37.3 v154.3,37.3 | v116.2,63.97 v128.9,63.97 | v128.9,57.62 v151.76,57.62
  Bottom 0.406: R2.2 R1.2 108.58,6.82 R23.2 | R23.2 C3.+ | v121.28,37.3 IC1.20 116.2,34.76 | C5.2 v151.76,57.62 R5.2 151.76,67.78 131.44,67.78 R4.2 | v128.9,57.62 IC2.17 v128.9,63.97 | C4.2 R15.2 v154.3,37.3 | 116.2,42.38 R6.2 | C17.1 67.94,16.98 R66.2 | R23.2 108.58,19.52 99.69,19.52 99.69,27.14 | 111.12,27.14 R19.2
  Bottom 1.016: v116.2,63.97 116.2,42.38 116.2,34.76 116.2,27.14 111.12,27.14 99.69,27.14 83.18,27.14 R18.2 67.94,24.6 | 57.78,24.6 IC7.OUT | D11.A 57.78,24.6 | 57.78,24.6 60.32,24.6 D12.C 67.94,29.68 67.94,27.14 | 67.94,27.14 67.94,24.6 | 67.94,27.14 C20.+ | 67.94,24.6 C17.1
+12V
  Bottom 0.406: 113.66,94.45 136.52,94.45 C7.2 140.33,84.29 IC3.8 | C9.2 113.66,94.45 | 57.78,32.22 70.48,32.22 70.48,28.41 | 70.48,28.41 R17.2 | 70.48,28.41 114.93,28.41 114.93,70.32 108.58,70.32 108.58,84.29 C9.2 | IC4.8 117.47,84.29 C9.2 | R37.2 42.54,90.64 R40.2 R27.2 106.04,90.64 R30.2 113.66,94.45
  Bottom 1.016: IC5.OUT 40,24.6 | 40,24.6 D9.A | 40,24.6 C15.1 43.81,24.6 C18.+ 43.81,32.22 R63.2 53.97,32.22 | 53.97,32.22 IC7.IN | 53.97,32.22 57.78,32.22 D11.C
+18V
  Bottom 0.406: R57.2 R29.2 R28.2 R39.2 R38.2 46.35,95.72 R47.2 D18.C
  Bottom 1.016: 17.14,95.72 9.52,95.72 C26.+ | 17.14,95.72 R74.2 | 17.14,95.72 D18.C
-12V  (via drill 0.61 pad 1.42)
  Top 0.406: v136.52,71.59 v136.52,75.4
  Bottom 0.406: IC4.4 C10.1 v136.52,75.4 | v136.52,71.59 147.95,71.59 IC3.4 C8.1 156.84,75.4 156.84,10.63 147.95,1.74 60.32,1.74 D13.A R16.2
  Bottom 1.016: IC6.OUT 40,9.36 D10.C 43.81,6.82 | 43.81,6.82 R64.1 R65.1 D13.A | C16.2 43.81,14.44 C19.- 43.81,6.82
-18V
  Bottom 0.406: R72.1 51.43,60.16 57.78,60.16 57.78,37.3 83.18,37.3 | R61.1 R62.1 83.18,47.46 83.18,37.3 | R52.E 83.18,36.03 83.18,37.3
  Bottom 1.016: R72.1 C25.- 32.38,58.89 D17.A
A
  Bottom 0.406: R50.S 107.31,61.43 93.34,61.43 CON3.5
ADJHR
  Bottom 0.406: IC1.3 126.36,14.44 CON1.2 R2.1
ADJMIN
  Bottom 0.406: IC1.2 R1.1 123.82,9.36 CON1.4
DX1
  Bottom 0.406: R39.1 T6.C 55.24,85.56 55.24,74.13 56.51,72.86 90.8,72.86 98.42,65.24 CON3.3
DX2
  Bottom 0.406: R38.1 T5.C 52.7,85.56 52.7,72.86 55.24,70.32 90.8,70.32 95.88,65.24 CON3.4
DY1
  Bottom 0.406: R29.1 T4.C 92.07,85.56 92.07,76.67 103.5,65.24 CON3.1
DY2
  Bottom 0.406: R28.1 T3.C 89.53,85.56 89.53,76.67 100.96,65.24 CON3.2
FIL1
  Bottom 1.016: CON3.10 73.02,63.97 73.02,55.08 R61.2 66.67,55.08 66.67,42.38 73.02,42.38 74.29,41.11 X1.2
FIL2
  Bottom 1.016: CON3.9 83.18,61.43 75.56,61.43 R62.2 75.56,51.27 69.21,51.27 69.21,44.92 75.56,44.92 79.33,41.15 X1.1
G1
  Bottom 0.406: R60.1 R59.1 85.72,57.62 CON3.8 85.72,66.51 71.75,66.51 62.86,57.62 C12.1
G3
  Bottom 0.406: CON3.6 90.8,58.89 98.42,58.89 98.42,38.57 R51.S
GND
  Bottom 0.406: 99.69,13.17 95.88,13.17 94.61,14.44
  Bottom 1.016: R69.2 C24.+ 32.38,38.57 D16.C
  pour Bottom (isolate 0.4): 0.63,93.18 5.71,93.18 6.98,94.45 6.98,99.53 153.03,99.53 153.03,93.18 159.38,93.18 159.38,6.82 154.3,6.82 153.03,5.55 153.03,0.47 6.98,0.47 6.98,3.01 3.17,6.82 0.63,6.82
K
  Bottom 0.406: R54.1 R53.2 88.26,56.35 CON3.7
N$1
  Bottom 0.406: 139.06,65.24 149.22,65.24 149.22,37.3 141.6,37.3 IC1.12 | 139.06,65.24 R4.1 | IC2.14 136.52,65.24 139.06,65.24
N$2
  Bottom 0.406: IC1.13 139.06,38.57 147.95,38.57 147.95,63.97 R5.1 141.6,63.97 139.06,61.43 IC2.13
N$3
  Bottom 0.406: IC2.12 141.6,62.7 146.68,62.7 146.68,39.84 136.52,39.84 IC1.14
N$4
  Bottom 0.406: IC2.11 145.41,60.16 145.41,41.11 133.98,41.11 IC1.15
N$5
  Bottom 0.406: IC1.16 131.44,42.38 144.14,42.38 IC2.10
N$6
  Bottom 0.406: IC1.17 128.9,44.92 141.6,44.92 IC2.9
N$7
  Bottom 0.406: IC1.18 126.36,46.19 139.06,46.19 IC2.8
N$8
  Bottom 0.406: IC1.19 123.82,47.46 136.52,47.46 IC2.7
N$9
  Bottom 0.406: IC1.9 141.6,29.68 150.49,29.68 150.49,66.51 135.25,66.51 135.25,56.35 133.98,55.08 IC2.6
N$10
  Bottom 0.406: 132.71,60.16 IC2.16 | 132.71,60.16 IC2.15 | 132.71,60.16 132.71,50 135.25,50 135.25,55.08 142.87,55.08 142.87,43.65 130.17,43.65 130.17,32.22 139.06,32.22 IC1.8
N$11
  Bottom 0.406: IC2.2 123.82,55.08 125.09,56.35 125.09,72.86 123.82,72.86 123.82,77.94 142.87,77.94 IC3.2
N$12
  Bottom 0.406: IC4.2 120.01,60.16 IC2.20
N$13
  Bottom 0.406: IC2.3 126.36,55.08 127.63,56.35 127.63,71.59 133.98,71.59 R8.2 140.33,74.13 IC3.1
N$14
  Bottom 0.406: IC2.19 123.82,57.62 118.74,57.62 118.74,72.86 117.47,72.86 117.47,74.13 | 117.47,74.13 IC4.1 | 117.47,74.13 R12.2
N$15
  Bottom 0.406: 125.09,50 122.55,50 122.55,55.08 118.74,55.08 R6.1 118.74,46.19 121.28,46.19 C6.1 | 125.09,50 128.9,50 IC2.4 128.9,55.08 130.17,56.35 130.17,69.05 154.3,69.05 R7.2 | 125.09,50 125.09,55.08 126.36,56.35 IC2.18 126.36,72.86 R11.2
N$16
  Bottom 0.406: CON2.4 89.53,19.52 R22.2 89.53,24.6 D2.A
N$17
  Bottom 0.406: IC3.5 R9.2
N$18
  Bottom 0.406: IC4.5 R13.2
N$19
  Bottom 0.406: R8.1 133.98,80.48 145.41,80.48 IC3.6 145.41,89.37 | 145.41,89.37 R10.1 R10.2 | 145.41,89.37 154.3,89.37 R7.1
N$20
  Bottom 0.406: R12.1 111.12,80.48 122.55,80.48 IC4.6 122.55,89.37 | 122.55,89.37 R14.1 R14.2 | 122.55,89.37 131.44,89.37 R11.1
N$21
  Bottom 0.406: 121.28,20.79 IC1.1 | 121.28,20.79 R3.2 | 121.28,20.79 D1.C 121.28,11.9 C3.-
N$22
  Bottom 0.406: R31.2 74.29,84.29 74.29,88.1 86.99,88.1 T3.B
N$23
  Bottom 0.406: R31.1 75.56,76.67 R33.2
N$24
  Bottom 0.406: R34.2 86.99,83.02 | 86.99,83.02 R32.1 | 86.99,83.02 T3.E
N$25
  Bottom 0.406: C1.2 Q1.2 144.14,20.79 131.44,20.79 IC1.5
N$26
  Bottom 0.406: IC1.4 128.9,20.79 131.44,18.25 Q1.1 139.06,13.17 | C2.2 139.06,13.17 | 139.06,13.17 L1.1
N$27
  Bottom 0.406: R41.2 43.81,84.29 43.81,88.1 50.16,88.1 T5.B
N$28
  Bottom 0.406: CON2.8 R16.1
N$29
  Bottom 0.406: CON2.6 R18.1
N$30
  Bottom 0.406: R17.1 73.02,19.52 73.02,16.98 CON2.5
N$31
  Bottom 0.406: T2.C 106.04,10.63 106.04,4.28 R23.1 146.68,4.28 146.68,23.33 133.98,23.33 IC1.6
N$32
  Bottom 0.406: R25.1 R24.2 100.96,11.9 C11.1
N$33
  Bottom 0.406: T4.E R32.2 94.61,77.94 R35.2
N$34
  Bottom 0.406: R41.1 42.54,81.75 R43.2
N$35
  Bottom 0.406: T1.B 97.15,18.25 R20.1
N$36
  Bottom 0.406: R21.2 R20.2 D2.C
N$37
  Bottom 0.406: T4.B 94.61,88.1 106.04,88.1 | 106.04,88.1 R30.1 D4.C | R36.2 111.12,88.1 106.04,88.1
N$38
  Bottom 0.406: 89.53,6.82 R26.2 | 89.53,6.82 93.34,6.82 R25.2 | D3.C 86.99,4.28 86.99,6.82 89.53,6.82
N$39
  Bottom 1.016: D19.C D18.A
N$40
  Bottom 0.406: IC1.7 136.52,29.68 118.74,29.68 R19.1 118.74,22.06 103.5,22.06 T1.C
N$41
  Bottom 0.406: R24.1 97.15,8.09 T2.B
N$42
  Bottom 1.016: D20.C 32.38,76.67 28.57,72.86 D19.A
N$43
  Bottom 0.406: R31.3 79.37,86.83 R27.1
N$44
  Bottom 0.406: R44.2 50.16,83.02 T5.E R42.1
N$45
  Bottom 0.406: R41.3 42.54,86.83 R37.1
N$46
  Bottom 0.406: 57.78,83.02 R45.2 | 57.78,83.02 T6.E | R42.2 57.78,83.02
N$48
  Bottom 0.406: 65.4,85.56 65.4,88.1 57.78,88.1 T6.B | 65.4,85.56 R40.1 | 65.4,85.56 D5.C R46.2
N$49
  Bottom 0.406: T7.E 50.16,70.32 R48.2
N$50
  Bottom 0.406: R47.1 32.38,83.02 34.92,80.48 34.92,67.78 T7.C 62.86,67.78 C12.2
N$52
  Bottom 0.406: R52.A 92.07,36.03 R53.1
N$53
  Bottom 0.406: R51.E 94.61,48.73 R54.2
N$54
  Bottom 0.406: T7.B 50.16,65.24 60.32,65.24 60.32,41.11 R49.2
N$55
  Bottom 0.406: R51.A 100.96,36.03 R55.1
N$56
  Bottom 0.406: R50.A 109.85,62.7 99.69,72.86 99.69,79.21 102.23,81.75 R57.1
N$57
  Bottom 0.406: R55.2 R56.1
N$58
  Bottom 0.406: R50.E R58.2
N$59
  Bottom 0.254: 1.9,100.8 -0.64,100.8 -0.64,98.26
N$60  (via drill 1.02 pad 2.54)
  other vias: 3.17,96.99
N$61  (via drill 1.02 pad 2.54)
  other vias: 3.17,3.01
N$62
  Bottom 0.254: 1.9,-0.8 -0.64,-0.8 -0.64,1.74
N$63
  Bottom 0.406: R65.2 52.7,9.36 D14.K
N$64
  Bottom 1.016: R73.2 R74.1
N$65
  Bottom 1.016: D15.C 5.71,63.97 5.71,79.21 9.52,79.21 | 9.52,79.21 C23.+ | 9.52,79.21 17.14,79.21 | 17.14,79.21 R67.2 | 17.14,79.21 R73.1
N$66  (via drill 1.02 pad 2.54)
  other vias: 156.84,96.99
N$67
  Bottom 1.016: R67.1 R68.2
N$68
  Bottom 1.016: 17.14,29.68 D7.C | 17.14,29.68 C21.+ IC5.IN 40,29.68 D9.C | C13.1 17.14,29.68
N$69
  Bottom 0.406: R60.2 79.37,53.81 D6.A
N$70
  Bottom 0.406: R59.2 86.99,50 D6.C R52.S
N$71  (via drill 1.02 pad 2.54)
  other vias: 156.84,3.01
N$72
  Bottom 1.016: C24.- 42.54,48.73 | 42.54,48.73 C25.+ | 42.54,48.73 55.24,48.73 | 55.24,48.73 R71.2 | 55.24,48.73 R70.1
N$73
  Bottom 0.254: 158.11,100.8 160.65,100.8 160.65,98.26
N$74
  Bottom 0.406: R70.2 55.24,41.11 51.43,44.92 R69.1
N$75
  Bottom 1.016: D8.A 17.14,9.36 | 17.14,9.36 C22.- 26.03,11.9 IC6.IN 40,11.9 D10.A | 17.14,9.36 C14.2
N$76
  Bottom 0.254: 160.65,1.74 160.65,-0.8 158.11,-0.8
N$77
  Bottom 0.406: C28.2 149.22,13.17 L1.2
N$78
  Bottom 0.406: R72.2 51.43,52.54 55.24,56.35 R71.1
N$80
  Bottom 1.016: C27.2 20.95,46.19 D16.A D17.C
N$82
  Bottom 1.016: C27.1 20.95,53.81 D15.A 5.71,53.81 X3.1
SYNC
  Bottom 0.406: D8.C 9.52,4.28 D3.A
  Bottom 1.016: D8.C 1.9,9.36 1.9,22.06 | 1.9,22.06 1.9,29.68 D7.A | X2.1 1.9,22.02 1.9,22.06
XCTRL
  Bottom 0.406: IC3.7 142.87,86.83 139.06,86.83 R10.3 139.06,95.72 R46.1
YCTRL
  Bottom 0.406: IC4.7 120.01,86.83 116.2,86.83 R14.3 116.2,91.91 R36.1
ZCTRL  (via drill 0.61 pad 1.42)
  Top 0.406: v113.66,30.95 v140.33,30.95
  Bottom 0.406: v140.33,30.95 144.14,30.95 IC1.11 R15.1 | v113.66,30.95 113.66,29.68 71.75,29.68 71.75,33.49 R49.1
